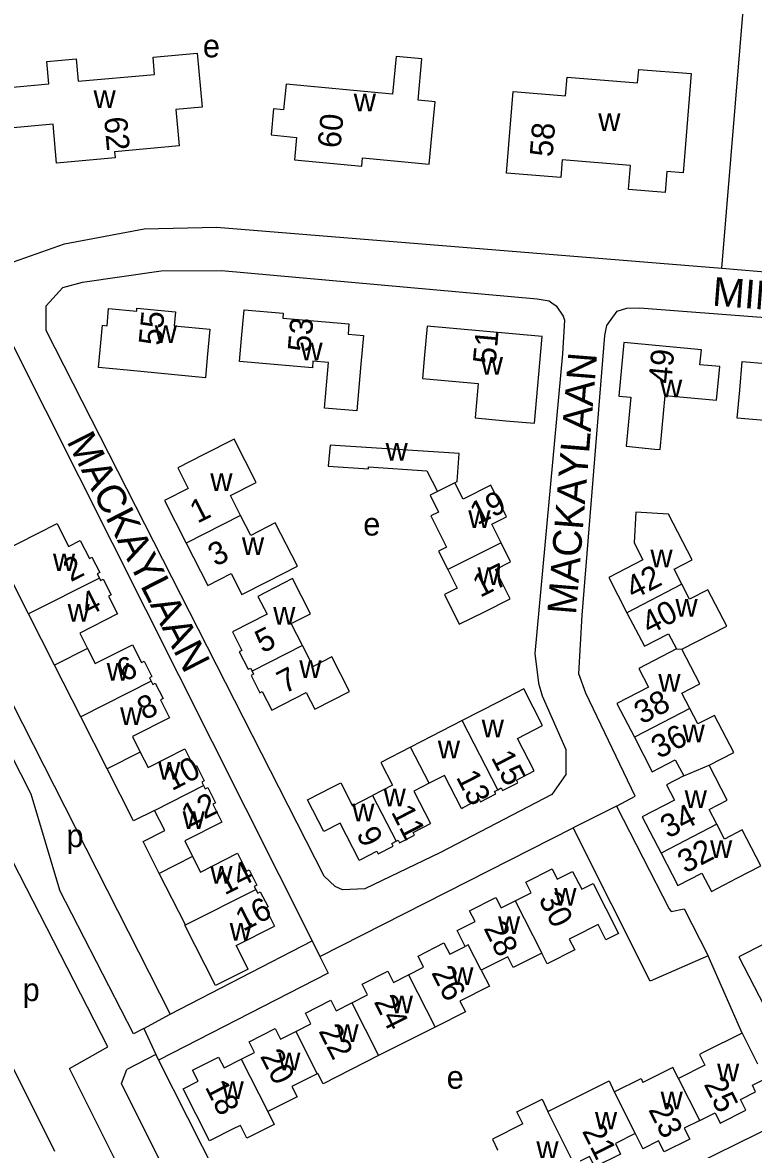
# Model space of a CAD drawing. Extents: x 162427 to 165104, y 384242 to 386287.
# Drawn here: x 163785.5 to 163912.8, y 385039.2 to 385235.6 of the extents above; entities that cross this region are included whole.
import ezdxf

# ---------------------------------------------------------------- set-up
doc = ezdxf.new("R2010")
doc.units = 0
for name, color, linetype in [('BLT_Basislijn', 7, 'Continuous'), ('BLT_Bebouwing', 7, 'Continuous'), ('BLT_Centroide', 7, 'Continuous'), ('BLT_Huisnummer', 7, 'Continuous'), ('BLT_Huisnummer_ tussenligend', 7, 'Continuous'), ('BLT_Huisnummer_reeks', 7, 'Continuous'), ('BLT_Onderverdeling_panden', 7, 'Continuous'), ('BLT_Straatnaam', 7, 'Continuous')]:
    doc.layers.add(name, color=color, linetype=linetype)

msp = doc.modelspace()

# ---------------------------------------------------------------- linework, layer by layer
at = {"layer": 'BLT_Basislijn'}
for p, q in [((163795.92, 385190.37), (163809.61, 385192.33)), ((163809.61, 385192.33), (163820.1, 385192.41)), ((163820.1, 385192.41), (163875.08, 385187.48)), ((163907.27, 385192.8), (163916.82, 385191.96)), ((163792.49, 385189.44), (163795.92, 385190.37)), ((163789.59, 385186.22), (163792.49, 385189.44)), ((163789.56, 385181.91), (163789.59, 385186.22)), ((163875.08, 385187.48), (163877.15, 385187.11)), ((163877.15, 385187.11), (163877.65, 385186.78)), ((163877.65, 385186.78), (163878.37, 385186.22)), ((163878.37, 385186.22), (163879.6, 385184.45)), ((163879.86, 385183.75), (163879.48, 385177.88)), ((163879.6, 385184.45), (163879.86, 385183.75)), ((163837.99, 385086.86), (163789.56, 385181.91)), ((163879.48, 385177.88), (163874.7, 385125.62)), ((163874.7, 385125.62), (163875.31, 385120.5)), ((163875.31, 385120.5), (163875.94, 385118.28)), ((163875.94, 385118.28), (163880.08, 385108.89)), ((163880.08, 385108.89), (163880.08, 385104.53)), ((163880.08, 385104.53), (163877.63, 385101.09)), ((163877.63, 385101.09), (163858.27, 385090.94)), ((163888.92, 385099.03), (163881.33, 385095.27)), ((163837.24, 385072.85), (163881.33, 385095.27)), ((163858.27, 385090.94), (163845.08, 385084.61)), ((163839.89, 385085.05), (163837.99, 385086.86)), ((163841.2, 385084.44), (163839.89, 385085.05)), ((163845.08, 385084.61), (163841.2, 385084.44)), ((163811.18, 385062.76), (163835.89, 385075.55)), ((163835.89, 385075.55), (163837.24, 385072.85)), ((163837.24, 385072.85), (163838.69, 385069.96)), ((163910.8, 385059.49), (163904.85, 385072.93)), ((163838.69, 385069.96), (163809.12, 385054.76)), ((163777.04, 385066.9), (163791.03, 385038.89)), ((163806.56, 385060.29), (163808.66, 385055.75)), ((163808.66, 385055.75), (163809.12, 385054.76)), ((163809.12, 385054.76), (163833.54, 385006.59)), ((163870.49, 385020.87), (163918.79, 385044.59))]:
    msp.add_line(p, q, dxfattribs=at)
for points in [[(163907.27, 385192.8), (163911.27, 385241.28), (163808.18, 385250.92), (163791.47, 385252.26), (163765.36, 385238.93), (163724.92, 385218.99)], [(163752.77, 385178.48), (163781.92, 385193.2), (163792.74, 385197.05), (163806.65, 385199.65), (163819.21, 385199.97), (163907.27, 385192.8)], [(163888.92, 385099.03), (163892.17, 385100.78), (163883.54, 385118.73), (163882.35, 385122.09), (163882.92, 385132.31), (163886.87, 385181.05), (163887.24, 385182.8), (163888.99, 385185.31), (163890.71, 385185.84), (163892.89, 385185.88), (163936.03, 385182.55), (163944.89, 385181.59), (163946.8, 385179.9), (163947.05, 385176.26), (163943.23, 385134.98), (163943.39, 385129.54), (163944.73, 385123.43), (163945.53, 385121.28), (163955.66, 385101.15)], [(163757.88, 385172.36), (163778.33, 385182.39), (163781.84, 385181.88), (163783.67, 385179.61), (163835.89, 385075.55)], [(163757.88, 385172.36), (163760.95, 385167.29), (163773.97, 385141.82), (163774.13, 385140.71), (163772.42, 385139.59), (163772.58, 385138.73), (163811.18, 385062.76)], [(163755.36, 385170.98), (163768.88, 385145.16), (163767.23, 385139.82), (163786.89, 385101.19), (163791.91, 385084.45)], [(163888.92, 385099.03), (163898.1, 385081.15), (163898.44, 385080.66), (163900.7, 385081.14), (163904.85, 385072.93)], [(163904.85, 385072.93), (163894.78, 385068.55), (163881.33, 385095.27)], [(163799.94, 385022.17), (163805.03, 385024.78), (163805.84, 385028.91), (163793.63, 385053.32), (163800.33, 385057.11), (163783.75, 385089.4), (163769.51, 385082.08)], [(163806.56, 385060.29), (163804.78, 385059.38), (163791.91, 385084.45)], [(163806.56, 385060.29), (163811.18, 385062.76)], [(163808.66, 385055.75), (163803.64, 385053.17)], [(163833.54, 385006.59), (163826.68, 385002.57), (163802.71, 385050.7), (163803.64, 385053.17)]]:
    msp.add_lwpolyline(points, dxfattribs=at)
at = {"layer": 'BLT_Bebouwing'}
for p, q in [((163798.46, 385139.52), (163798.83, 385138.8)), ((163798.83, 385138.8), (163799.05, 385138.36)), ((163791.03, 385123.63), (163786.51, 385132.55)), ((163795.6, 385114.61), (163791.03, 385123.63)), ((163807.54, 385121.39), (163807.83, 385120.81)), ((163807.83, 385120.81), (163808.13, 385120.23)), ((163800.2, 385105.55), (163795.6, 385114.61)), ((163862.04, 385113.97), (163853.04, 385109.34)), ((163816.66, 385103.22), (163816.96, 385102.62)), ((163816.96, 385102.62), (163817.25, 385102.06)), ((163861.9, 385098.64), (163862.17, 385098.78)), ((163844.1, 385089.61), (163844.37, 385089.75)), ((163813.83, 385078.33), (163809.27, 385087.32)), ((163825.82, 385085.06), (163826.08, 385084.54)), ((163826.08, 385084.54), (163826.41, 385083.9)), ((163827.76, 385081.24), (163829.34, 385078.13)), ((163862.54, 385074.59), (163861.14, 385077.35)), ((163857.33, 385060.53), (163847.47, 385055.57)), ((163910.8, 385059.49), (163913.48, 385054.15)), ((163892.14, 385041.98), (163893.47, 385039.33))]:
    msp.add_line(p, q, dxfattribs=at)
msp.add_lwpolyline([(163781.88, 385224.17), (163790.05, 385224.91), (163789.7, 385228.81), (163794.79, 385229.27), (163795.14, 385225.37), (163808.45, 385226.57), (163808.18, 385229.56), (163815.89, 385230.26), (163816.74, 385220.88), (163812.17, 385220.46), (163812.74, 385214.11), (163801.49, 385213.09), (163801.59, 385212.02), (163791.39, 385211.1), (163790.78, 385217.91), (163782.52, 385217.16)], close=True, dxfattribs=at)
for points in [[(163856.73, 385215.89), (163857.3, 385221.79), (163854.33, 385222.07), (163855.02, 385229.27), (163850.52, 385229.7), (163849.89, 385223.1), (163831.34, 385224.89), (163830.91, 385220.41), (163829.19, 385220.57), (163828.75, 385216.02), (163833.18, 385215.6), (163832.8, 385211.7), (163844.54, 385210.57), (163844.68, 385212.02), (163856.25, 385210.91), (163856.73, 385215.89)], [(163900.94, 385214.39), (163900.53, 385209.41), (163897.67, 385209.64), (163897.37, 385205.97), (163890.98, 385206.49), (163891.32, 385210.7), (163879.45, 385211.67), (163879.2, 385208.6), (163869.73, 385209.37), (163870.13, 385214.35), (163870.88, 385223.61), (163880.03, 385222.86), (163880.29, 385226.1), (163892.58, 385225.11), (163892.77, 385227.45), (163901.93, 385226.7), (163900.94, 385214.39)], [(163817.62, 385177.21), (163817.29, 385173.67), (163803.67, 385175.01), (163798.7, 385175.48), (163799.39, 385182.85), (163800.17, 385182.77), (163800.45, 385185.77), (163805.33, 385185.31), (163805.38, 385185.85), (163812.11, 385185.22), (163811.88, 385182.78), (163818.09, 385182.19), (163817.62, 385177.21)], [(163844.38, 385176.08), (163843.66, 385167.91), (163838.03, 385168.4), (163838.73, 385176.39), (163836.04, 385176.62), (163835.94, 385175.43), (163823.25, 385176.54), (163823.6, 385180.56), (163824.04, 385185.55), (163830.86, 385184.95), (163830.79, 385184.11), (163842.3, 385183.1), (163842.14, 385181.3), (163844.81, 385181.07), (163844.38, 385176.08)], [(163864.81, 385172.73), (163864.27, 385166.7), (163869.64, 385166.22), (163874.62, 385165.77), (163875.98, 385180.89), (163855.92, 385182.68), (163855.48, 385177.7), (163855.11, 385173.6), (163864.81, 385172.73)], [(163906.9, 385175.64), (163903.44, 385175.97), (163903.69, 385178.56), (163890.17, 385179.85), (163889.28, 385170.5), (163891.39, 385170.3), (163890.57, 385161.76), (163895.55, 385161.28), (163896.48, 385161.19), (163897.38, 385170.62), (163906.34, 385169.77), (163906.9, 385175.64)], [(163924.03, 385171.74), (163923.39, 385164.43), (163914.6, 385165.21), (163914.7, 385166.26), (163909.93, 385166.68), (163910.36, 385171.55), (163910.8, 385176.53), (163919.05, 385175.81), (163919.17, 385177.18), (163924.47, 385176.72), (163924.03, 385171.74)], [(163823.42, 385149.7), (163821.65, 385153.19), (163826.13, 385155.47), (163822.3, 385162.99), (163816.93, 385160.26), (163812.48, 385157.99), (163814.29, 385154.42), (163810.17, 385152.32), (163813.95, 385144.88)], [(163860.75, 385155.39), (163861.16, 385155.6), (163861.49, 385160.48), (163839.05, 385161.97), (163838.67, 385158.27), (163845.68, 385157.81), (163845.71, 385158.15), (163855.89, 385157.47), (163857.71, 385153.87)], [(163868.81, 385144.91), (163867.17, 385148.19), (163869.77, 385149.49), (163867.04, 385154.96), (163862.18, 385152.53), (163860.75, 385155.39)], [(163857.71, 385153.87), (163856.43, 385153.23), (163857.9, 385150.27), (163856.59, 385149.61), (163859.3, 385144.18), (163857.92, 385143.49), (163859.53, 385140.27)], [(163813.95, 385144.88), (163817.71, 385137.5), (163821.78, 385139.58), (163823.64, 385135.91), (163828.1, 385138.18), (163833.32, 385140.84), (163829.48, 385148.4), (163825.19, 385146.22), (163823.42, 385149.7)], [(163900.27, 385137.72), (163898.92, 385140.32), (163902.09, 385141.97), (163897.96, 385149.93), (163892.29, 385150.27), (163891.97, 385144.96), (163893.51, 385141.99), (163887.54, 385138.89), (163890.72, 385132.76)], [(163786.51, 385132.55), (163781.16, 385143.08), (163791.46, 385148.3), (163793.47, 385144.32), (163795.5, 385145.35), (163797.09, 385142.21)], [(163859.53, 385140.27), (163861.16, 385137.01), (163858.93, 385135.9), (163861.51, 385130.73), (163865.92, 385132.93), (163870.39, 385135.17), (163867.82, 385140.31), (163870.45, 385141.62), (163868.81, 385144.91)], [(163797.09, 385142.21), (163797.54, 385142.44), (163798.91, 385139.75), (163798.46, 385139.52)], [(163799.05, 385138.36), (163799.5, 385138.58), (163800.86, 385135.89), (163800.42, 385135.65)], [(163834.2, 385127.03), (163832.25, 385130.85), (163835.63, 385132.57), (163832.49, 385138.7), (163830.89, 385137.88), (163826.43, 385135.6), (163828.03, 385132.48), (163822.01, 385129.4), (163823.65, 385126.19), (163823.2, 385125.96), (163824.77, 385122.89), (163825.17, 385123.1), (163825.45, 385122.55)], [(163900.28, 385126.38), (163908.09, 385130.43), (163904.8, 385136.76), (163901.62, 385135.11), (163900.27, 385137.72)], [(163800.42, 385135.65), (163802.01, 385132.53), (163795.43, 385129.19), (163796.77, 385126.54)], [(163890.72, 385132.76), (163893.75, 385126.92), (163897.97, 385129.1), (163899.36, 385126.43)], [(163796.77, 385126.54), (163798.12, 385123.89), (163804.6, 385127.18), (163806.18, 385124.07)], [(163825.45, 385122.55), (163825.7, 385122.07), (163825.26, 385121.84), (163826.81, 385118.81), (163827.19, 385119.01), (163828.85, 385115.78), (163834.85, 385118.85), (163836.35, 385115.93), (163842.41, 385119.03), (163839.33, 385125.05), (163836.07, 385123.39), (163834.2, 385127.03)], [(163899.36, 385126.43), (163892.77, 385123.01), (163894.45, 385119.79), (163888.96, 385116.94), (163892.02, 385111.05)], [(163901.67, 385116.06), (163900.27, 385118.75), (163903.4, 385120.37), (163900.28, 385126.38)], [(163806.18, 385124.07), (163806.63, 385124.29), (163807.99, 385121.62), (163807.54, 385121.39)], [(163808.13, 385120.23), (163808.57, 385120.46), (163809.93, 385117.79), (163809.48, 385117.56)], [(163874.59, 385105.17), (163871.67, 385110.86), (163876.03, 385113.11), (163872.75, 385119.47), (163868.31, 385117.19), (163862.04, 385113.97)], [(163809.48, 385117.56), (163811.06, 385114.45), (163804.58, 385111.16), (163805.95, 385108.46)], [(163905.02, 385106.17), (163909.31, 385108.4), (163905.96, 385114.86), (163903.07, 385113.36), (163901.67, 385116.06)], [(163892.02, 385111.05), (163895.13, 385105.05), (163899.14, 385107.13), (163900.6, 385104.32)], [(163853.04, 385109.34), (163847.86, 385106.67), (163849.91, 385102.7), (163846.43, 385100.91)], [(163805.95, 385108.46), (163807.32, 385105.77), (163813.72, 385109.01), (163815.31, 385105.89)], [(163808.45, 385098.31), (163804.8, 385096.47), (163800.2, 385105.55)], [(163815.31, 385105.89), (163815.75, 385106.12), (163817.11, 385103.44), (163816.66, 385103.22)], [(163868.25, 385101.91), (163868.83, 385102.21), (163869.05, 385101.76), (163871.72, 385103.13), (163871.49, 385103.58), (163874.59, 385105.17)], [(163906.38, 385095.89), (163905.03, 385098.48), (163908.17, 385100.11), (163905.02, 385106.17)], [(163861.9, 385098.64), (163858.93, 385104.41), (163856.27, 385103.05)], [(163900.6, 385104.32), (163897.6, 385102.76), (163898.98, 385100.11), (163893.39, 385097.2), (163896.68, 385090.86)], [(163817.25, 385102.06), (163817.7, 385102.28), (163819.05, 385099.61), (163818.61, 385099.38)], [(163844.1, 385089.61), (163840.77, 385096.09), (163837.9, 385094.62), (163835.07, 385100.13), (163839.52, 385102.42), (163840.89, 385103.12), (163842.95, 385099.12), (163846.43, 385100.91)], [(163856.27, 385103.05), (163853.61, 385101.68), (163856.52, 385096)], [(163862.17, 385098.78), (163865.01, 385100.24), (163865.24, 385099.8), (163867.9, 385101.17), (163867.67, 385101.61), (163868.25, 385101.91)], [(163818.61, 385099.38), (163820.19, 385096.26), (163813.7, 385092.97), (163815.07, 385090.27)], [(163809.27, 385087.32), (163806.46, 385092.87), (163810.24, 385094.79), (163808.45, 385098.31)], [(163850.54, 385092.92), (163850.88, 385093.1), (163851.11, 385092.67), (163853.71, 385094.01), (163853.49, 385094.44), (163856.52, 385096)], [(163896.68, 385090.86), (163899.61, 385085.21), (163903.77, 385087.37), (163905.42, 385084.19), (163909.86, 385086.49), (163914.02, 385088.65), (163910.79, 385094.89), (163907.72, 385093.3), (163906.38, 385095.89)], [(163844.37, 385089.75), (163847.15, 385091.18), (163847.37, 385090.74), (163849.98, 385092.08), (163849.75, 385092.52), (163850.54, 385092.92)], [(163815.07, 385090.27), (163816.44, 385087.56), (163822.9, 385090.83), (163824.47, 385087.72)], [(163824.47, 385087.72), (163824.92, 385087.95), (163826.27, 385085.29), (163825.82, 385085.06)], [(163871.26, 385082.55), (163874.04, 385083.96), (163873.11, 385085.8), (163877.68, 385088.12), (163878.59, 385086.33), (163881.26, 385087.68), (163882.85, 385084.55), (163884.86, 385085.57), (163889.27, 385076.87), (163887.04, 385075.75), (163885.69, 385078.41), (163881.45, 385076.26), (163880.67, 385075.87), (163881.62, 385074), (163876.82, 385071.57), (163875.87, 385073.43)], [(163826.41, 385083.9), (163826.85, 385084.13), (163828.21, 385081.47), (163827.76, 385081.24)], [(163861.14, 385077.35), (163864.26, 385078.93), (163863.31, 385080.8), (163867.87, 385083.12), (163868.8, 385081.3), (163871.26, 385082.55)], [(163824.75, 385070.65), (163819.07, 385067.76), (163813.73, 385078.28), (163813.83, 385078.33)], [(163824.75, 385070.65), (163822.67, 385074.75), (163829.34, 385078.13)], [(163920.92, 385074.32), (163918.29, 385072.97), (163916.68, 385076.09), (163914.67, 385075.05), (163910.22, 385072.76), (163914.62, 385064.24), (163917.54, 385065.74), (163919.69, 385061.57), (163925.87, 385064.76)], [(163852.68, 385069.66), (163855.31, 385071), (163854.34, 385072.92), (163858.84, 385075.21), (163859.85, 385073.23), (163862.54, 385074.59)], [(163875.87, 385073.43), (163870.93, 385070.92), (163869.98, 385072.8), (163865.34, 385070.45)], [(163842.82, 385064.74), (163845.56, 385066.13), (163844.6, 385068.01), (163849.07, 385070.28), (163850.06, 385068.33), (163852.68, 385069.66)], [(163865.34, 385070.45), (163866.76, 385067.64), (163861.64, 385065.04), (163862.58, 385063.19), (163857.33, 385060.53)], [(163833.04, 385059.75), (163835.67, 385061.09), (163834.71, 385062.96), (163839.13, 385065.21), (163840.08, 385063.35), (163842.82, 385064.74)], [(163823.55, 385054.92), (163825.86, 385056.09), (163824.91, 385057.97), (163829.46, 385060.28), (163830.4, 385058.42), (163833.04, 385059.75)], [(163910.8, 385059.49), (163904.09, 385056.14), (163903.33, 385055.76), (163904.27, 385053.89), (163899.71, 385051.6)], [(163828.17, 385045.8), (163829.3, 385043.58), (163824.53, 385041.16), (163823.39, 385043.41), (163822.49, 385042.96), (163818.04, 385040.69), (163813.43, 385049.77), (163816.05, 385051.1), (163815.07, 385053.02), (163819.6, 385055.32), (163820.57, 385053.41), (163823.55, 385054.92)], [(163847.47, 385055.57), (163837.79, 385050.65), (163836.87, 385052.47), (163836.76, 385052.41)], [(163836.76, 385052.41), (163832.35, 385050.17), (163833.26, 385048.38), (163828.17, 385045.8)], [(163899.71, 385051.6), (163898.72, 385053.51), (163893.51, 385050.9)], [(163876.96, 385045.81), (163887.62, 385051.15), (163888.51, 385049.23)], [(163888.51, 385049.23), (163893.17, 385051.57), (163893.51, 385050.9)], [(163903.39, 385044.28), (163906.07, 385045.62), (163906.98, 385043.8), (163911.43, 385046.03), (163910.48, 385047.92), (163913.13, 385049.25), (163912.56, 385050.4), (163914.79, 385051.52)], [(163872.61, 385043.66), (163871.55, 385045.76), (163875.98, 385047.97), (163876.96, 385045.81)], [(163903.39, 385044.28), (163900.71, 385042.93), (163901.67, 385041.01), (163897.2, 385038.77), (163896.23, 385040.71), (163893.47, 385039.33)], [(163872.61, 385043.66), (163867.29, 385040.99), (163868.2, 385039.17), (163868.05, 385039.09)], [(163892.14, 385041.98), (163888.7, 385040.25), (163889.62, 385038.41), (163885.14, 385036.16), (163884.21, 385038.01), (163881.54, 385036.67)]]:
    msp.add_lwpolyline(points, dxfattribs=at)
at = {"layer": 'BLT_Onderverdeling_panden'}
for p, q in [((163823.42, 385149.7), (163813.95, 385144.88)), ((163868.81, 385144.91), (163859.53, 385140.27)), ((163798.83, 385138.8), (163786.51, 385132.55)), ((163900.27, 385137.72), (163890.72, 385132.76)), ((163834.2, 385127.03), (163825.45, 385122.55)), ((163796.77, 385126.54), (163791.03, 385123.63)), ((163899.36, 385126.43), (163900.28, 385126.38)), ((163807.83, 385120.81), (163795.6, 385114.61)), ((163901.67, 385116.06), (163892.02, 385111.05)), ((163868.25, 385101.91), (163862.04, 385113.97)), ((163856.27, 385103.05), (163853.04, 385109.34)), ((163805.95, 385108.46), (163800.2, 385105.55)), ((163900.6, 385104.32), (163905.02, 385106.17)), ((163808.45, 385098.31), (163816.96, 385102.62)), ((163846.43, 385100.91), (163850.54, 385092.92)), ((163906.38, 385095.89), (163896.68, 385090.86)), ((163815.07, 385090.27), (163809.27, 385087.32)), ((163813.83, 385078.33), (163826.08, 385084.54)), ((163871.26, 385082.55), (163875.87, 385073.43)), ((163852.68, 385069.66), (163857.33, 385060.53)), ((163842.82, 385064.74), (163847.47, 385055.57)), ((163833.04, 385059.75), (163836.76, 385052.41)), ((163823.55, 385054.92), (163828.17, 385045.8)), ((163903.39, 385044.28), (163899.71, 385051.6)), ((163888.51, 385049.23), (163892.14, 385041.98)), ((163881.54, 385036.67), (163876.96, 385045.81))]:
    msp.add_line(p, q, dxfattribs=at)
for points in [[(163860.75, 385155.39), (163857.71, 385153.87)], [(163865.34, 385070.45), (163863.09, 385074.87), (163862.54, 385074.59)]]:
    msp.add_lwpolyline(points, dxfattribs=at)

# ---------------------------------------------------------------- texts
at = {"layer": 'BLT_Centroide'}
for s, p in [('e', (163816.86, 385229.54)), ('w', (163797.82, 385220.72)), ('w', (163843.14, 385220.12)), ('w', (163885.73, 385216.72)), ('w', (163808.48, 385179.75)), ('w', (163833.85, 385176.72)), ('w', (163865.27, 385174.22)), ('w', (163896.48, 385170.27)), ('w', (163848.69, 385159.28)), ('w', (163818.16, 385153.95)), ('w', (163863.09, 385147.53)), ('e', (163844.79, 385146.2)), ('w', (163823.67, 385142.81)), ('w', (163790.75, 385140)), ('w', (163894.81, 385140.66)), ('w', (163864.69, 385137.58)), ('w', (163899.17, 385132.06)), ('w', (163793.3, 385131.22)), ('w', (163829.11, 385130.69)), ('w', (163800.11, 385120.91)), ('w', (163833.66, 385121.38)), ('w', (163896.19, 385119)), ('w', (163802.45, 385113.19)), ('w', (163865.43, 385111.03)), ('w', (163900.42, 385110.19)), ('w', (163857.78, 385107.36)), ('w', (163809.08, 385103.66)), ('w', (163848.34, 385099.01)), ('w', (163900.78, 385098.7)), ('w', (163842.88, 385096.38)), ('w', (163813.33, 385095.08)), ('p', (163793.1, 385091.9)), ('w', (163905.2, 385090.03)), ('w', (163818.16, 385085.53)), ('w', (163878.08, 385081.72)), ('w', (163868.26, 385076.78)), ('w', (163821.53, 385075.62)), ('w', (163860.12, 385067.88)), ('p', (163785.47, 385065.07)), ('w', (163849.59, 385062.95)), ('w', (163840.12, 385057.94)), ('w', (163829.98, 385052.98)), ('w', (163906.42, 385051.11)), ('e', (163859.32, 385049.8)), ('w', (163820.12, 385048.02)), ('w', (163896.59, 385046.2)), ('w', (163885.15, 385042.69)), ('w', (163874.95, 385037.56))]:
    msp.add_text(s, height=4, dxfattribs=at).set_placement(p)
at = {"layer": 'BLT_Huisnummer'}
for s, rotation, p in [('62', 275.1747, (163799.65, 385219.04)), ('60', 84.4978, (163840.81, 385213.6)), ('55', 84.6053, (163809.63, 385179.22)), ('53', 85.0179, (163835.6, 385178.08)), ('51', 84.8852, (163867.85, 385175.96)), ('49', 84.5597, (163898.43, 385172.58)), ('1', 26.9761, (163815.91, 385148.24)), ('19', 26.5386, (163864.68, 385147.98)), ('3', 26.9761, (163819.06, 385140.72)), ('2', 26.8952, (163793.85, 385138.06)), ('17', 26.5292, (163865.15, 385135.34)), ('42', 27.4153, (163891.84, 385134.99)), ('5', 26.9761, (163827.26, 385125.63)), ('6', 26.8808, (163803.17, 385120.59)), ('7', 27.0968, (163831.09, 385118.58)), ('36', 27.4189, (163896.28, 385107.23)), ('10', 26.8926, (163811.45, 385101.64)), ('15', 297.2143, (163866.99, 385107.54)), ('9', 297.2118, (163843.49, 385094.22)), ('32', 27.4106, (163900.88, 385087.25)), ('30', 296.9252, (163875.24, 385082.85)), ('16', 26.8907, (163823.86, 385077.14)), ('26', 296.9262, (163856.58, 385070.02)), ('22', 296.923, (163836.93, 385059.85)), ('18', 296.9226, (163817.15, 385050.11)), ('25', 296.6245, (163904.04, 385050.58))]:
    msp.add_text(s, height=4, rotation=rotation, dxfattribs=at).set_placement(p)
at = {"layer": 'BLT_Huisnummer_ tussenligend'}
for s, rotation, p in [('4', 26.8952, (163796.83, 385132.06)), ('40', 27.4189, (163894.62, 385128.86)), ('38', 27.4189, (163893.3, 385113.23)), ('8', 26.8808, (163806.72, 385113.94)), ('13', 297.2118, (163860.89, 385104.1)), ('12', 26.8926, (163814.46, 385095.33)), ('34', 27.4106, (163897.87, 385093.35)), ('11', 297.2118, (163849.57, 385098.04)), ('14', 26.8926, (163820.65, 385083.45)), ('28', 296.9262, (163865.68, 385077.78)), ('24', 296.923, (163846.57, 385064.97)), ('20', 296.9226, (163826.77, 385055.48)), ('23', 296.6212, (163894.39, 385046.15)), ('21', 296.6212, (163882.84, 385042.42))]:
    msp.add_text(s, height=4, rotation=rotation, dxfattribs=at).set_placement(p)
at = {"layer": 'BLT_Huisnummer_reeks'}
msp.add_text('58', height=4, rotation=85.3756, dxfattribs=at).set_placement((163877.76, 385212.09))
at = {"layer": 'BLT_Straatnaam'}
for s, rotation, p in [('MINISTERLAAN', 355.5702, (163905.48, 385186.29)), ('MACKAYLAAN', 85.3647, (163881.83, 385132.32)), ('MACKAYLAAN', 297.0542, (163793.05, 385162.64))]:
    msp.add_text(s, height=5, rotation=rotation, dxfattribs=at).set_placement(p)

doc.saveas('drawing.dxf')
